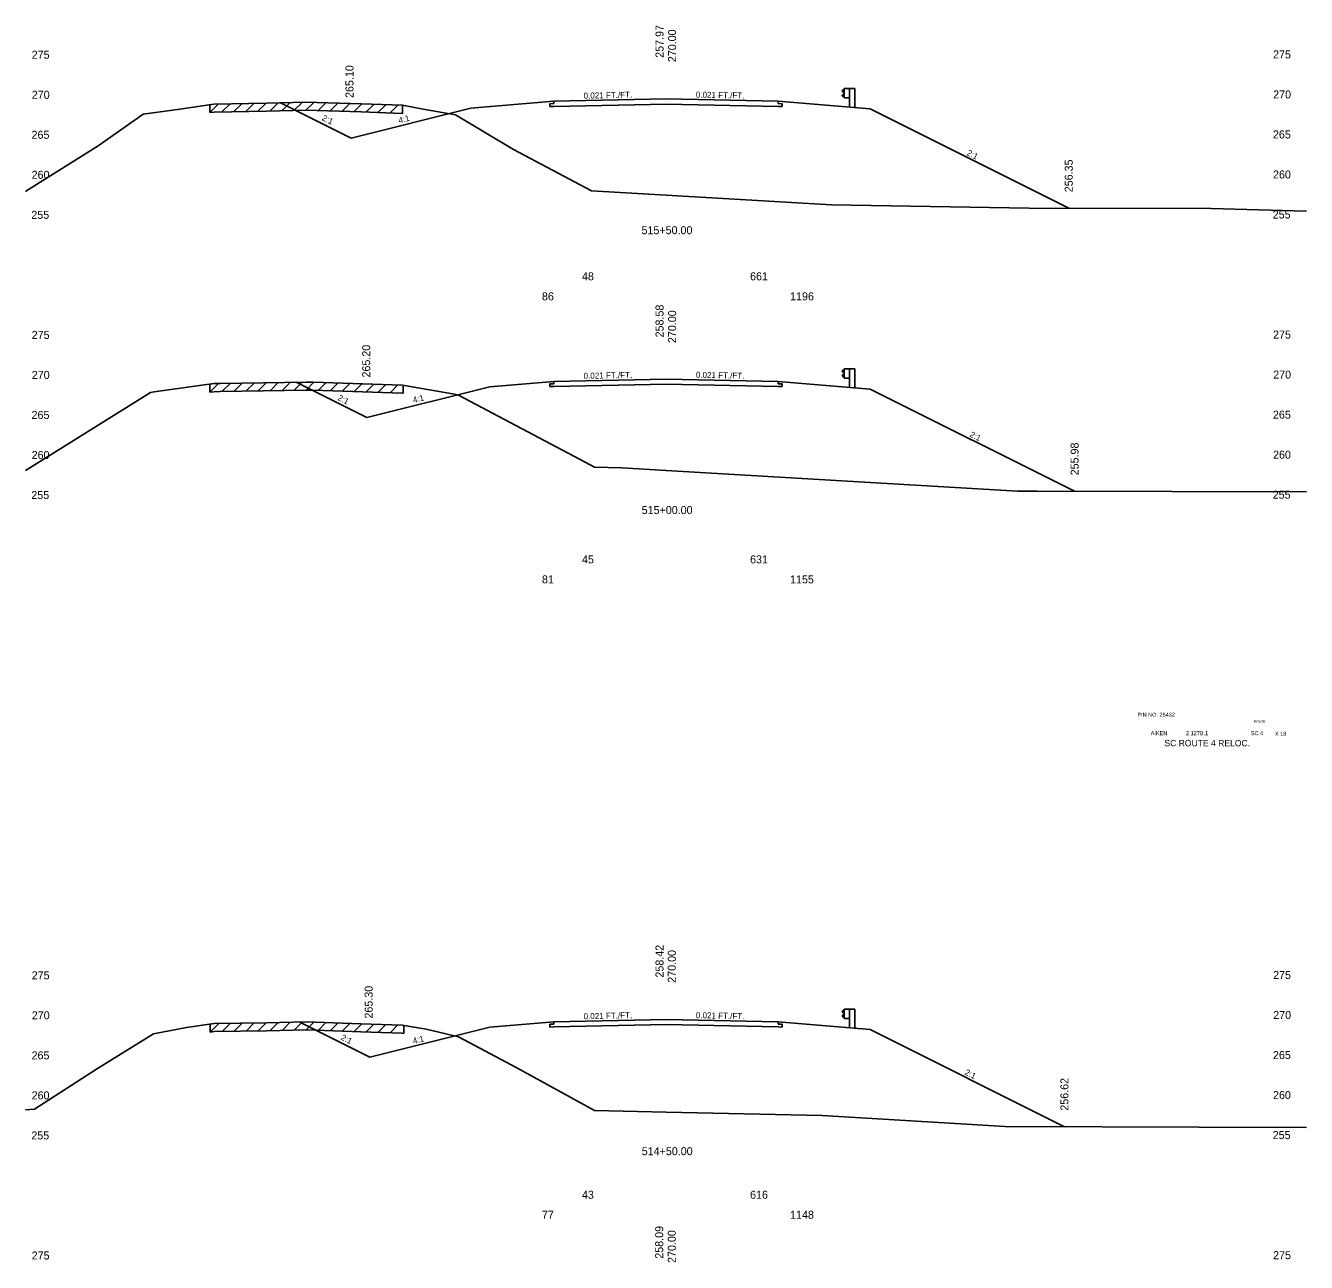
# Model space of a CAD drawing. Extents: x 2967 to 4323, y -3677 to -817.
# Drawn here: x 3188.8 to 3348.8, y -1690.2 to -1535.7 of the extents above; entities that cross this region are included whole.
import ezdxf

# ---------------------------------------------------------------- set-up
doc = ezdxf.new("R2010")
doc.units = 0
for name, color, linetype in [('Level 1', 7, 'Continuous'), ('Level 10', 7, 'Continuous'), ('Level 11', 7, 'Continuous'), ('Level 12', 7, 'Continuous'), ('Level 20', 7, 'Continuous'), ('Level 24', 7, 'Continuous'), ('Level 3', 7, 'Continuous'), ('Level 32', 7, 'Continuous'), ('Level 33', 7, 'Continuous'), ('Level 59', 7, 'Continuous'), ('Level 6', 7, 'Continuous'), ('Level 60', 7, 'Continuous'), ('Level 61', 7, 'Continuous'), ('Level 7', 7, 'Continuous')]:
    doc.layers.add(name, color=color, linetype=linetype)

msp = doc.modelspace()

# ---------------------------------------------------------------- linework, layer by layer
at = {"layer": 'Level 11'}
for p, q in [((3254.76, -1545.43), (3254.26, -1545.44)), ((3254.26, -1545.44), (3254.26, -1545.78)), ((3254.76, -1545.13), (3254.76, -1545.43)), ((3282.76, -1545.43), (3282.76, -1545.13)), ((3283.26, -1545.44), (3282.76, -1545.43)), ((3283.26, -1545.78), (3283.26, -1545.44)), ((3254.26, -1545.78), (3254.76, -1545.77)), ((3282.76, -1545.77), (3283.26, -1545.78)), ((3254.76, -1580.43), (3254.26, -1580.44)), ((3254.26, -1580.44), (3254.26, -1580.78)), ((3254.26, -1580.78), (3254.76, -1580.77)), ((3254.76, -1580.13), (3254.76, -1580.43)), ((3282.76, -1580.43), (3282.76, -1580.13)), ((3283.26, -1580.44), (3282.76, -1580.43)), ((3282.76, -1580.77), (3283.26, -1580.78)), ((3283.26, -1580.78), (3283.26, -1580.44)), ((3254.76, -1660.43), (3254.26, -1660.44)), ((3254.26, -1660.44), (3254.26, -1660.78)), ((3254.26, -1660.78), (3254.76, -1660.77)), ((3254.76, -1660.13), (3254.76, -1660.43)), ((3282.76, -1660.43), (3282.76, -1660.13)), ((3283.26, -1660.44), (3282.76, -1660.43)), ((3282.76, -1660.77), (3283.26, -1660.78)), ((3283.26, -1660.78), (3283.26, -1660.44))]:
    msp.add_line(p, q, dxfattribs=at)
at = {"layer": 'Level 12'}
for p, q in [((3268.76, -1545.48), (3254.76, -1545.77)), ((3282.76, -1545.77), (3268.76, -1545.48)), ((3268.76, -1580.48), (3254.76, -1580.77)), ((3282.76, -1580.77), (3268.76, -1580.48)), ((3268.76, -1660.48), (3254.76, -1660.77)), ((3282.76, -1660.77), (3268.76, -1660.48))]:
    msp.add_line(p, q, dxfattribs=at)
at = {"layer": 'Level 24'}
for p, q in [((3291.03, -1543.62), (3290.76, -1543.82)), ((3290.76, -1543.82), (3290.76, -1543.87)), ((3290.76, -1543.87), (3291.03, -1544.07)), ((3291.03, -1544.72), (3291.03, -1543.55)), ((3291.03, -1543.55), (3291.7, -1543.55)), ((3291.7, -1543.55), (3291.7, -1545.88)), ((3291.7, -1543.55), (3292.36, -1543.55)), ((3292.36, -1543.55), (3292.36, -1545.93)), ((3290.76, -1544.39), (3291.03, -1544.19)), ((3290.76, -1544.44), (3290.76, -1544.39)), ((3291.03, -1544.64), (3290.76, -1544.44)), ((3291.03, -1544.72), (3291.7, -1544.72)), ((3291.03, -1578.62), (3290.76, -1578.82)), ((3290.76, -1578.82), (3290.76, -1578.87)), ((3290.76, -1578.87), (3291.03, -1579.07)), ((3290.76, -1579.39), (3291.03, -1579.19)), ((3291.03, -1579.72), (3291.03, -1578.55)), ((3291.03, -1578.55), (3291.7, -1578.55)), ((3291.7, -1578.55), (3291.7, -1580.88)), ((3291.7, -1578.55), (3292.36, -1578.55)), ((3292.36, -1578.55), (3292.36, -1580.93)), ((3290.76, -1579.44), (3290.76, -1579.39)), ((3291.03, -1579.64), (3290.76, -1579.44)), ((3291.03, -1579.72), (3291.7, -1579.72)), ((3291.03, -1658.62), (3290.76, -1658.82)), ((3290.76, -1658.82), (3290.76, -1658.87)), ((3290.76, -1658.87), (3291.03, -1659.07)), ((3290.76, -1659.39), (3291.03, -1659.19)), ((3291.03, -1659.72), (3291.03, -1658.55)), ((3291.03, -1658.55), (3291.7, -1658.55)), ((3291.7, -1658.55), (3291.7, -1660.88)), ((3291.7, -1658.55), (3292.36, -1658.55)), ((3292.36, -1658.55), (3292.36, -1660.93)), ((3290.76, -1659.44), (3290.76, -1659.39)), ((3291.03, -1659.64), (3290.76, -1659.44)), ((3291.03, -1659.72), (3291.7, -1659.72))]:
    msp.add_line(p, q, dxfattribs=at)
at = {"layer": 'Level 59'}
for p, q in [((3254.76, -1545.13), (3268.76, -1544.84)), ((3268.76, -1544.84), (3282.76, -1545.13)), ((3254.76, -1580.13), (3268.76, -1579.84)), ((3268.76, -1579.84), (3282.76, -1580.13)), ((3254.76, -1660.13), (3268.76, -1659.84)), ((3268.76, -1659.84), (3282.76, -1660.13))]:
    msp.add_line(p, q, dxfattribs=at)
at = {"layer": 'Level 6'}
for p, q in [((3244.36, -1546), (3254.76, -1545.13)), ((3282.76, -1545.13), (3290.76, -1545.8)), ((3290.76, -1545.8), (3294.26, -1546.09)), ((3246.76, -1580.8), (3254.76, -1580.13)), ((3282.76, -1580.13), (3290.76, -1580.8)), ((3290.76, -1580.8), (3294.26, -1581.09)), ((3246.76, -1660.8), (3254.76, -1660.13)), ((3282.76, -1660.13), (3290.76, -1660.8)), ((3290.76, -1660.8), (3294.26, -1661.09))]:
    msp.add_line(p, q, dxfattribs=at)
at = {"layer": 'Level 60'}
for p, q in [((3208.01, -1546.12), (3212.29, -1545.48)), ((3212.29, -1545.48), (3218.86, -1545.36)), ((3218.86, -1545.36), (3223.77, -1545.26)), ((3223.77, -1545.26), (3230.67, -1545.47)), ((3230.67, -1545.47), (3235.82, -1545.64)), ((3197.82, -1550.72), (3203.46, -1546.73)), ((3203.46, -1546.73), (3208.01, -1546.12)), ((3235.82, -1545.64), (3238.44, -1546.11)), ((3238.44, -1546.11), (3242.45, -1546.81)), ((3242.45, -1546.81), (3249.69, -1551.15)), ((3188.77, -1556.38), (3197.82, -1550.72)), ((3249.69, -1551.15), (3259.45, -1556.32)), ((3188.76, -1556.38), (3188.77, -1556.38)), ((3259.45, -1556.32), (3268.76, -1556.87)), ((3268.76, -1556.87), (3289.42, -1558.09)), ((3289.42, -1558.09), (3314.14, -1558.48)), ((3314.14, -1558.48), (3336.87, -1558.54)), ((3336.87, -1558.54), (3348.76, -1558.88)), ((3204.81, -1581.42), (3212.29, -1580.41)), ((3212.29, -1580.41), (3213.06, -1580.4)), ((3213.06, -1580.4), (3223.79, -1580.21)), ((3223.79, -1580.21), (3224.63, -1580.24)), ((3224.63, -1580.24), (3235.83, -1580.58)), ((3235.83, -1580.58), (3242.32, -1581.72)), ((3189.27, -1590.94), (3204.35, -1581.51)), ((3204.35, -1581.51), (3204.81, -1581.42)), ((3242.32, -1581.72), (3242.84, -1581.83)), ((3242.84, -1581.83), (3258.66, -1590.21)), ((3258.66, -1590.21), (3259.83, -1590.86)), ((3188.76, -1591.27), (3189.27, -1590.94)), ((3259.83, -1590.86), (3263.26, -1590.94)), ((3263.26, -1590.94), (3268.76, -1591.26)), ((3268.76, -1591.26), (3312.65, -1593.84)), ((3312.65, -1593.84), (3315.11, -1593.85)), ((3315.11, -1593.85), (3348.76, -1593.94)), ((3208.84, -1660.82), (3212.3, -1660.35)), ((3212.3, -1660.35), (3218.85, -1660.24)), ((3218.85, -1660.24), (3223.81, -1660.15)), ((3223.81, -1660.15), (3230.64, -1660.38)), ((3230.64, -1660.38), (3235.8, -1660.53)), ((3235.8, -1660.53), (3238.8, -1661.06)), ((3197.75, -1665.97), (3204.72, -1661.61)), ((3204.72, -1661.61), (3208.84, -1660.82)), ((3238.8, -1661.06), (3242.83, -1661.99)), ((3242.83, -1661.99), (3250.13, -1665.86)), ((3189.86, -1671.05), (3197.75, -1665.97)), ((3250.13, -1665.86), (3259.83, -1671.22)), ((3188.76, -1671.14), (3189.86, -1671.05)), ((3259.83, -1671.22), (3268.76, -1671.42)), ((3268.76, -1671.42), (3288.26, -1671.85)), ((3288.26, -1671.85), (3311.14, -1673.19)), ((3311.14, -1673.19), (3335.31, -1673.3)), ((3335.31, -1673.3), (3348.76, -1673.34))]:
    msp.add_line(p, q, dxfattribs=at)
at = {"layer": 'Level 61'}
for p, q in [((3212.87, -1545.47), (3211.78, -1546.55)), ((3211.78, -1545.55), (3211.78, -1546.55)), ((3214.3, -1545.44), (3213.28, -1546.46)), ((3215.8, -1545.42), (3214.78, -1546.43)), ((3217.3, -1545.39), (3216.28, -1546.41)), ((3218.8, -1545.36), (3217.78, -1546.38)), ((3220.3, -1545.33), (3219.28, -1546.35)), ((3221.8, -1545.3), (3220.78, -1546.32)), ((3223.3, -1545.27), (3222.28, -1546.29)), ((3224.75, -1545.29), (3223.78, -1546.26)), ((3226.25, -1545.34), (3225.28, -1546.31)), ((3227.75, -1545.38), (3226.78, -1546.35)), ((3229.25, -1545.43), (3228.28, -1546.4)), ((3230.75, -1545.47), (3229.78, -1546.44)), ((3232.25, -1545.52), (3231.28, -1546.49)), ((3233.75, -1545.57), (3232.78, -1546.54)), ((3211.78, -1546.55), (3212.29, -1546.48)), ((3212.29, -1546.48), (3218.86, -1546.36)), ((3218.86, -1546.36), (3223.77, -1546.26)), ((3223.77, -1546.26), (3230.67, -1546.47)), ((3230.67, -1546.47), (3235.82, -1546.64)), ((3235.25, -1545.62), (3234.28, -1546.59)), ((3235.82, -1546.64), (3235.85, -1546.65)), ((3235.85, -1546.65), (3235.85, -1545.65)), ((3212.87, -1580.4), (3211.79, -1581.48)), ((3211.79, -1580.48), (3211.79, -1581.48)), ((3214.31, -1580.38), (3213.29, -1581.4)), ((3215.81, -1580.35), (3214.79, -1581.37)), ((3217.31, -1580.33), (3216.29, -1581.34)), ((3218.81, -1580.3), (3217.79, -1581.32)), ((3220.31, -1580.27), (3219.29, -1581.29)), ((3221.81, -1580.25), (3220.79, -1581.27)), ((3223.31, -1580.22), (3222.29, -1581.24)), ((3224.76, -1580.24), (3223.79, -1581.21)), ((3226.26, -1580.29), (3225.29, -1581.26)), ((3227.76, -1580.34), (3226.79, -1581.31)), ((3229.26, -1580.38), (3228.29, -1581.35)), ((3230.76, -1580.43), (3229.79, -1581.4)), ((3232.26, -1580.47), (3231.29, -1581.45)), ((3233.76, -1580.52), (3232.79, -1581.49)), ((3235.26, -1580.57), (3234.29, -1581.54)), ((3235.93, -1581.6), (3235.93, -1580.6)), ((3211.79, -1581.48), (3212.29, -1581.41)), ((3212.29, -1581.41), (3213.06, -1581.4)), ((3213.06, -1581.4), (3223.79, -1581.21)), ((3223.79, -1581.21), (3224.63, -1581.24)), ((3224.63, -1581.24), (3235.83, -1581.58)), ((3235.83, -1581.58), (3235.93, -1581.6)), ((3212.88, -1660.34), (3211.8, -1661.42)), ((3211.8, -1660.42), (3211.8, -1661.42)), ((3214.32, -1660.32), (3213.3, -1661.34)), ((3215.82, -1660.29), (3214.8, -1661.31)), ((3217.32, -1660.27), (3216.3, -1661.28)), ((3218.82, -1660.24), (3217.8, -1661.26)), ((3220.32, -1660.21), (3219.3, -1661.23)), ((3221.82, -1660.19), (3220.8, -1661.21)), ((3223.32, -1660.16), (3222.3, -1661.18)), ((3224.77, -1660.18), (3223.8, -1661.15)), ((3226.27, -1660.23), (3225.3, -1661.2)), ((3227.77, -1660.28), (3226.8, -1661.25)), ((3229.27, -1660.33), (3228.3, -1661.3)), ((3230.77, -1660.38), (3229.8, -1661.35)), ((3232.27, -1660.43), (3231.3, -1661.4)), ((3233.77, -1660.47), (3232.8, -1661.44)), ((3235.27, -1660.52), (3234.3, -1661.49)), ((3236.01, -1661.57), (3236.01, -1660.57)), ((3211.8, -1661.42), (3212.3, -1661.35)), ((3212.3, -1661.35), (3218.85, -1661.24)), ((3218.85, -1661.24), (3223.81, -1661.15)), ((3223.81, -1661.15), (3230.64, -1661.38)), ((3230.64, -1661.38), (3235.8, -1661.53)), ((3235.8, -1661.53), (3236.01, -1661.57))]:
    msp.add_line(p, q, dxfattribs=at)
at = {"layer": 'Level 7'}
for p, q in [((3220.59, -1545.33), (3229.41, -1549.74)), ((3244.36, -1546), (3229.41, -1549.74)), ((3294.26, -1546.09), (3319.07, -1558.5)), ((3222.55, -1580.23), (3231.37, -1584.65)), ((3246.76, -1580.8), (3231.37, -1584.65)), ((3294.26, -1581.09), (3319.8, -1593.86)), ((3223.01, -1660.17), (3231.77, -1664.55)), ((3246.76, -1660.8), (3231.77, -1664.55)), ((3294.26, -1661.09), (3318.53, -1673.23))]:
    msp.add_line(p, q, dxfattribs=at)

# ---------------------------------------------------------------- texts
at = {"layer": 'Level 1'}
for s, p in [('48', (3258.26, -1567.5)), ('661', (3279.26, -1567.5)), ('86', (3253.26, -1570)), ('1196', (3284.26, -1570)), ('45', (3258.26, -1602.86)), ('631', (3279.26, -1602.86)), ('81', (3253.26, -1605.36)), ('1155', (3284.26, -1605.36)), ('43', (3258.26, -1682.23)), ('616', (3279.26, -1682.23)), ('77', (3253.26, -1684.73)), ('1148', (3284.26, -1684.73))]:
    msp.add_text(s, height=1, dxfattribs=at).set_placement(p)
at = {"layer": 'Level 10'}
for s, p in [('257.97', (3268.45, -1539.7)), ('258.58', (3268.45, -1574.63)), ('258.42', (3268.45, -1654.6)), ('258.09', (3268.41, -1689.72))]:
    msp.add_text(s, height=1, rotation=90, dxfattribs=at).set_placement(p)
for s, p in [('515+50.00', (3265.7, -1561.74)), ('515+00.00', (3265.72, -1596.7)), ('514+50.00', (3265.73, -1676.79))]:
    msp.add_text(s, height=1, dxfattribs=at).set_placement(p)
at = {"layer": 'Level 20'}
for s, height, p in [('PIN NO. 26432', 0.5, (3327.65, -1622.02)), ('AIKEN', 0.5, (3329.31, -1624.32)), (' 2.127B.1', 0.5, (3333.53, -1624.32)), ('SC 4', 0.5, (3341.82, -1624.32)), ('ROUTE', 0.3, (3342.19, -1622.76)), ('X 18', 0.5, (3344.83, -1624.4)), ('SC ROUTE 4 RELOC.', 0.8, (3331.02, -1625.71))]:
    msp.add_text(s, height=height, dxfattribs=at).set_placement(p)
at = {"layer": 'Level 3'}
for s, p in [(' 275', (3189.15, -1539.82)), (' 275', (3344.23, -1539.78)), (' 270', (3189.16, -1544.82)), (' 270', (3344.24, -1544.78)), (' 265', (3344.21, -1549.78)), (' 265', (3189.13, -1549.82)), (' 260', (3189.14, -1554.82)), (' 260', (3344.22, -1554.78)), (' 255', (3189.1, -1559.82)), (' 255', (3344.18, -1559.78)), (' 275', (3189.15, -1574.82)), (' 275', (3344.23, -1574.78)), (' 270', (3189.16, -1579.82)), (' 270', (3344.24, -1579.78)), (' 265', (3189.13, -1584.82)), (' 265', (3344.21, -1584.78)), (' 260', (3344.22, -1589.78)), (' 260', (3189.14, -1589.82)), (' 255', (3189.1, -1594.82)), (' 255', (3344.18, -1594.78)), (' 275', (3189.15, -1654.82)), (' 275', (3344.23, -1654.78)), (' 270', (3189.16, -1659.82)), (' 270', (3344.24, -1659.78)), (' 265', (3189.13, -1664.82)), (' 265', (3344.21, -1664.78)), (' 260', (3344.22, -1669.78)), (' 260', (3189.14, -1669.82)), (' 255', (3189.1, -1674.82)), (' 255', (3344.18, -1674.78)), (' 275', (3189.15, -1689.82)), (' 275', (3344.23, -1689.78))]:
    msp.add_text(s, height=1, dxfattribs=at).set_placement(p)
at = {"layer": 'Level 32'}
for s, rotation, p in [('0.021 FT./FT.', 1.1916, (3258.47, -1544.81)), ('0.021 FT./FT.', 358.8084, (3272.48, -1544.67)), ('2:1', 333.435, (3225.71, -1547.45)), ('4:1', 14.0362, (3235.44, -1547.9)), ('2:1', 333.435, (3306.27, -1551.82)), ('0.021 FT./FT.', 1.1916, (3258.47, -1579.81)), ('0.021 FT./FT.', 358.8084, (3272.48, -1579.67)), ('2:1', 333.435, (3227.67, -1582.42)), ('4:1', 14.0362, (3237.23, -1582.83)), ('2:1', 333.435, (3306.63, -1587)), ('0.021 FT./FT.', 1.1916, (3258.47, -1659.81)), ('0.021 FT./FT.', 358.8084, (3272.48, -1659.67)), ('2:1', 333.435, (3228.07, -1662.32)), ('4:1', 14.0362, (3237.23, -1662.9)), ('2:1', 333.435, (3306, -1666.68))]:
    msp.add_text(s, height=0.75, rotation=rotation, dxfattribs=at).set_placement(p)
at = {"layer": 'Level 33'}
for s, p in [('265.10', (3229.72, -1544.72)), ('256.35', (3319.57, -1556.5)), ('265.20', (3231.81, -1579.64)), ('255.98', (3320.3, -1591.86)), ('265.30', (3232.11, -1659.72)), ('256.62', (3319.03, -1671.23))]:
    msp.add_text(s, height=1, rotation=90, dxfattribs=at).set_placement(p)
at = {"layer": 'Level 59'}
for p in [(3270.02, -1540.62), (3270.02, -1575.71), (3269.98, -1655.62), (3269.98, -1690.62)]:
    msp.add_text(' 270.00', height=1, rotation=90, dxfattribs=at).set_placement(p)

doc.saveas('drawing.dxf')
